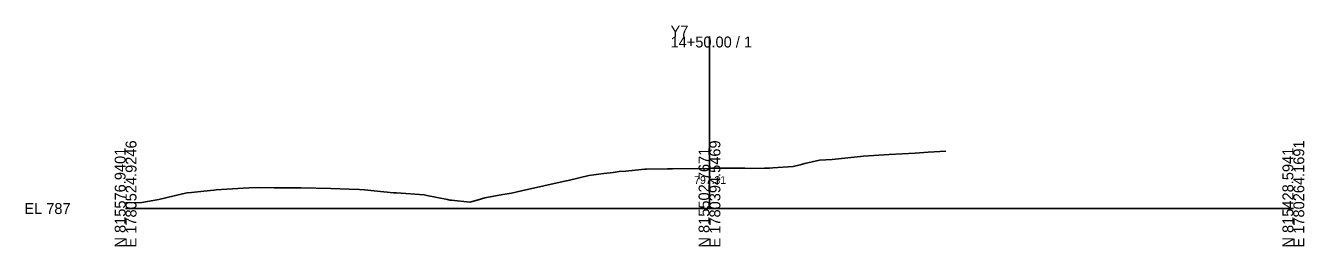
# Model space of a CAD drawing. Extents: x -26 to 2903, y -10 to 5536.
# Drawn here: x -25.7 to 302.8, y 4490.3 to 4546.9 of the extents above; entities that cross this region are included whole.
import ezdxf

# ---------------------------------------------------------------- set-up
doc = ezdxf.new("R2010")
doc.units = 0
for name, color, linetype in [('Exist Cross Section Cell', 7, 'Continuous'), ('Exist XS Center Line Elevation Label', 7, 'Continuous'), ('Exist XS Ground Line', 7, 'Continuous')]:
    doc.layers.add(name, color=color, linetype=linetype)

msp = doc.modelspace()

# ---------------------------------------------------------------- linework, layer by layer
at = {"layer": 'Exist Cross Section Cell'}
for p, q in [((150, 4500), (150, 4544.11)), ((0, 4500), (150, 4500)), ((150, 4500), (300, 4500))]:
    msp.add_line(p, q, dxfattribs=at)
at = {"layer": 'Exist XS Ground Line'}
for p, q in [((196.15, 4513.85), (202.84, 4514.19)), ((202.84, 4514.19), (206.16, 4514.46)), ((206.16, 4514.46), (210.73, 4514.7)), ((166.27, 4510.44), (171.51, 4510.78)), ((171.51, 4510.78), (173.27, 4511.18)), ((173.27, 4511.18), (174.5, 4511.59)), ((174.5, 4511.59), (178.26, 4512.41)), ((178.26, 4512.41), (181.54, 4512.6)), ((181.54, 4512.6), (189.55, 4513.42)), ((189.55, 4513.42), (196.15, 4513.85)), ((113.7, 4507.24), (119, 4508.44)), ((119, 4508.44), (122.82, 4508.97)), ((122.82, 4508.97), (125.28, 4509.23)), ((125.28, 4509.23), (126.83, 4509.53)), ((126.83, 4509.53), (128.49, 4509.63)), ((128.49, 4509.63), (129.25, 4509.68)), ((129.25, 4509.68), (133.42, 4510.09)), ((133.42, 4510.09), (133.79, 4510.13)), ((133.79, 4510.13), (139.25, 4510.2)), ((139.25, 4510.2), (140.52, 4510.21)), ((140.52, 4510.21), (150, 4510.31)), ((150, 4510.31), (150.52, 4510.32)), ((150.52, 4510.32), (151.19, 4510.32)), ((151.19, 4510.32), (159.1, 4510.38)), ((159.1, 4510.38), (160.43, 4510.3)), ((160.43, 4510.3), (164.1, 4510.33)), ((164.1, 4510.33), (164.81, 4510.35)), ((164.81, 4510.35), (165.39, 4510.35)), ((165.39, 4510.35), (166.27, 4510.44)), ((16.96, 4504.14), (20.11, 4504.49)), ((20.11, 4504.49), (22.7, 4504.75)), ((22.7, 4504.75), (23.28, 4504.8)), ((23.28, 4504.8), (30.23, 4505.23)), ((30.23, 4505.23), (31.72, 4505.28)), ((31.72, 4505.28), (34.24, 4505.37)), ((34.24, 4505.37), (38.21, 4505.35)), ((38.21, 4505.35), (45.11, 4505.29)), ((45.11, 4505.29), (52.73, 4505.11)), ((52.73, 4505.11), (57.43, 4504.99)), ((57.43, 4504.99), (60.05, 4504.85)), ((60.05, 4504.85), (61.38, 4504.78)), ((61.38, 4504.78), (68.81, 4504.07)), ((99.18, 4503.97), (101.69, 4504.54)), ((101.69, 4504.54), (113.2, 4507.12)), ((113.2, 4507.12), (113.7, 4507.24)), ((0, 4501.44), (4.14, 4501.58)), ((4.14, 4501.58), (8.58, 4502.35)), ((8.58, 4502.35), (14.63, 4503.74)), ((14.63, 4503.74), (15.84, 4504.03)), ((15.84, 4504.03), (16.96, 4504.14)), ((68.81, 4504.07), (69.59, 4504)), ((69.59, 4504), (76.72, 4503.49)), ((76.72, 4503.49), (77.41, 4503.37)), ((77.41, 4503.37), (82.72, 4502.34)), ((82.72, 4502.34), (83.3, 4502.19)), ((83.3, 4502.19), (83.73, 4502.16)), ((83.73, 4502.16), (88.46, 4501.64)), ((88.46, 4501.64), (90.28, 4502.12)), ((90.28, 4502.12), (92.29, 4502.76)), ((92.29, 4502.76), (96.95, 4503.57)), ((96.95, 4503.57), (99.18, 4503.97))]:
    msp.add_line(p, q, dxfattribs=at)

# ---------------------------------------------------------------- texts
at = {"layer": 'Exist Cross Section Cell'}
for s, p in [('Y7', (140, 4544.11)), ('14+50.00 / 1', (140, 4541.31)), ('EL 787', (-26, 4498.6))]:
    msp.add_text(s, height=2.8, dxfattribs=at).set_placement(p)
for s, p in [('N 815576.9401', (0, 4490)), ('E 1780524.9246', (2.8, 4490)), ('N 815502.7671', (150, 4490)), ('E 1780394.5469', (152.8, 4490)), ('N 815428.5941', (300, 4490)), ('E 1780264.1691', (302.8, 4490))]:
    msp.add_text(s, height=2.8, rotation=90, dxfattribs=at).set_placement(p)
at = {"layer": 'Exist XS Center Line Elevation Label'}
msp.add_text('797.31', height=2, dxfattribs=at).set_placement((146.08, 4506.31))

doc.saveas('drawing.dxf')
